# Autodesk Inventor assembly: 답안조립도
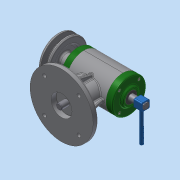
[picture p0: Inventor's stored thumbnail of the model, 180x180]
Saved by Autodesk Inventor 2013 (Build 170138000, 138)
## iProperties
Created: 2017-02
Part Number: 답안조립도
Document SubType Name: Assembly
Designer: dgall
Author: dgall
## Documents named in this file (16)
- C:\Users\dgall\Desktop\370207V1030\답안조립도.iam
- C:\Users\dgall\Desktop\370207V1030\본체.ipt
- C:\Users\dgall\Desktop\370207V1030\V벨트풀리.ipt
- C:\Users\dgall\Desktop\370207V1030\가변스프링.ipt
- C:\Users\dgall\Desktop\370207V1030\뒤커버.ipt
- C:\Users\dgall\Desktop\370207V1030\레버.ipt
- C:\Users\dgall\Desktop\370207V1030\멈춤나사 M3x8.ipt
- C:\Users\dgall\Desktop\370207V1030\베어링 6201.ipt
- C:\Users\dgall\Desktop\370207V1030\베어링 6202.ipt
- C:\Users\dgall\Desktop\370207V1030\본체상부커버.ipt
- C:\Users\dgall\Desktop\370207V1030\볼트 M3x0.5x8.ipt
- C:\Users\dgall\Desktop\370207V1030\슬라이드.ipt
- C:\Users\dgall\Desktop\370207V1030\앞커버.ipt
- C:\Users\dgall\Desktop\370207V1030\오일실 12 22 7.ipt
- C:\Users\dgall\Desktop\370207V1030\키 4 x 4 x 18.ipt
- C:\Users\dgall\Desktop\370207V1030\편심축.ipt
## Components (2 placed, 2 different names)
1. V벨트풀리:1
2. 가변스프링:1
